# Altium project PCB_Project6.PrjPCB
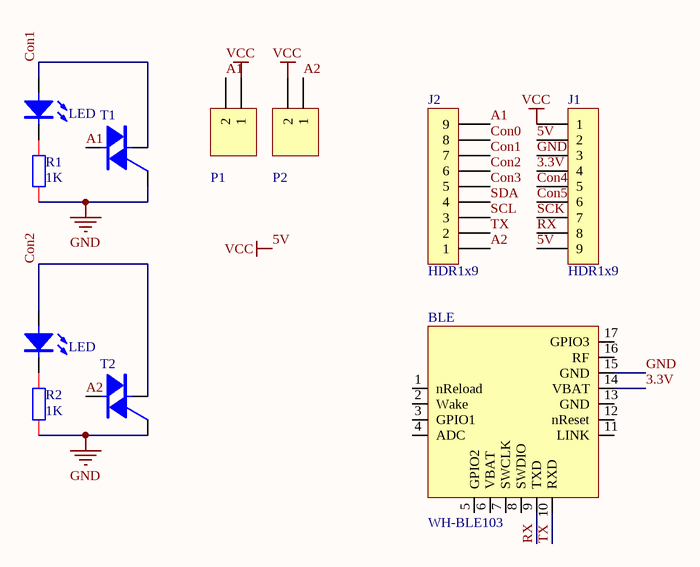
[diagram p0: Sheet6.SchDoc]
1 sheet, 11 parts. Net scope: global (net labels, ports and power ports of the same name join across sheets).
Board files: PCB6.PcbDoc, PCB6_1.PcbDoc

## Sheet Sheet6.SchDoc
size A4

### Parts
BLE  WH-BLE103  [PCBComponent_1]
J1  HDR1x9  [PIN-9-2.54-1.0]
J2  HDR1x9  [PIN-9-2.54-1.0]
LED1  LED  [LED-0805]
LED2  LED  [LED-0805]
P1  Header 2  [HDR2X1_A]  (value not drawn)
P2  Header 2  [HDR2X1_A]  (value not drawn)
R1  value 1K  [0603]  (hidden comment: Res2)
R2  value 1K  [0603]  (hidden comment: Res2)
T1  BT136S-600E  [TO-252]  (value not drawn)
T2  BT136S-600E  [TO-252]  (value not drawn)

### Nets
5V: J1.1 J1.2 J1.9 P1.1 P2.2  [also labelled VCC]
GND: BLE.15(GND) J1.3 R1.1 R2.1 T1.3(G) T2.3(G)
3.3V: BLE.14(VBAT) J1.4
A1: J2.9 P1.2 T1.4(T2)
A2: J2.1 P2.1 T2.4(T2)
Con0: J2.8
Con1: J2.7 LED1.1(A) T1.1(T1)
Con2: J2.6 LED2.1(A) T2.1(T1)
Con3: J2.5
Con4: J1.5
Con5: J1.6
RX: BLE.9(TXD) J1.8
SCK: J1.7
SCL: J2.3
SDA: J2.4
TX: BLE.10(RXD) J2.2
NetLED1_2: LED1.2(C) R1.2
NetLED2_2: LED2.2(C) R2.2

Not connected (* = marked no-connect by the designer): BLE 1(nReload) 2(Wake) 3(GPIO1) 4(ADC) 5(GPIO2) 6(VBAT) 7(SWCLK) 8(SWDIO) 11(LINK) 12(nReset) 13(GND) 16(RF) 17(GPIO3)

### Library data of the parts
J1 J2 = HDR1x9: Connector
P1 P2 = Header 2: 接插件
R1 R2 = Res2: Resistor
T1 T2 = BT136S-600E: Triac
